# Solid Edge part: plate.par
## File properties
Author: Deepak Maini
Template: Normal.par
Last saved by: CADCIM
Revision: 2
Application: Solid Edge
Accuracy: 0.99
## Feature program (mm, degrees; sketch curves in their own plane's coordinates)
sketch for "unnamed Protrusion 1" plane through (0, 0, 0) normal (0, 0, 1) x-axis (1, 0, 0)
  circle centre (0, 0) radius 59.0444
extrude "unnamed Protrusion 1" add finite 19.05 along -normal
sketch for "Hole_1" plane through (0, 0, 0) normal (0, 0, 1) x-axis (0, 1, 0)
  hole centre (-28.483, 27.7745) bore radius 8
hole "Hole_1" diameter 16 through
sketch for "ExtrudedCutout_1" plane through (0, 0, 0) normal (0, 0, 1) x-axis (0, 1, 0)
  line (-59.0916, 45.0627) -> (-29.6658, 45.0627)
  arc centre (-29.6658, 29.4258) radius 15.6369 from (-29.6658, 45.0627) to (-14.0289, 29.4258) cw
  line (-14.0289, 29.4258) -> (-14.0289, 27.7745)
  arc centre (-28.483, 27.7745) radius 14.4541 from (-14.0289, 27.7745) to (-28.483, 13.3204) cw
  line (-28.483, 13.3204) -> (-59.0916, 13.3204)
  line (-59.0916, 13.3204) -> (-59.0916, 45.0627)
extrude "ExtrudedCutout_1" cut finite 6.35 along -normal
pattern "unnamed Pattern 1" of "Hole_1"
hole "unnamed Hole 1" through
hole "unnamed Hole 2" through
hole "unnamed Hole 3" through
mirror "unnamed Mirror 1" of "ExtrudedCutout_1" about plane through (0, 0, 0) normal (0, -1, 0)
extrude "unnamed Cutout 1" cut finite 6.35
mirror "unnamed Mirror 2" of "ExtrudedCutout_1" about plane through (0, 0, 0) normal (1, 0, 0)
extrude "unnamed Cutout 2" cut finite 6.35
mirror "unnamed Mirror 3" of "unnamed Mirror 1" about plane through (0, 0, 0) normal (1, 0, 0)
extrude "unnamed Cutout 3" cut finite 6.35
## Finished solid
Body 1: solid body, 31 faces, 81 edges, 48 vertices.
  Faces by surface: plane 18, cylinder 13
  Edges by curve: line 48, circle 33
Bounding box of the edges (mm): 118.089 x 118.089 x 19.050, from (-59.0444, -59.0444, -19.05) to (59.0444, 59.0444, 0).
Cylindrical faces by radius (mm): R8 x4, R14.4541 x4, R15.6369 x4, R59.0444 x1
Planar faces by outward normal: +x 4, +y 2, +z 5, -x 4, -y 2, -z 1
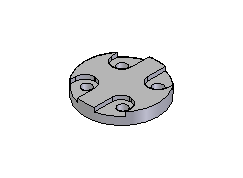
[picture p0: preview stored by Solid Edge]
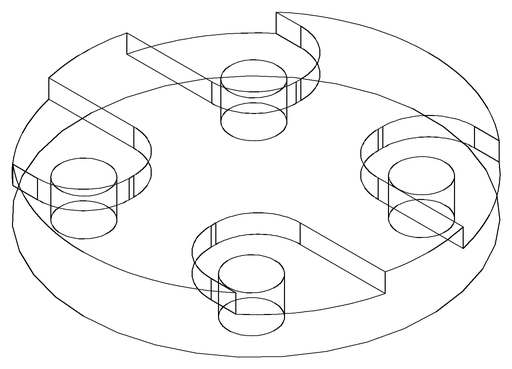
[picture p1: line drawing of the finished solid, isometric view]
